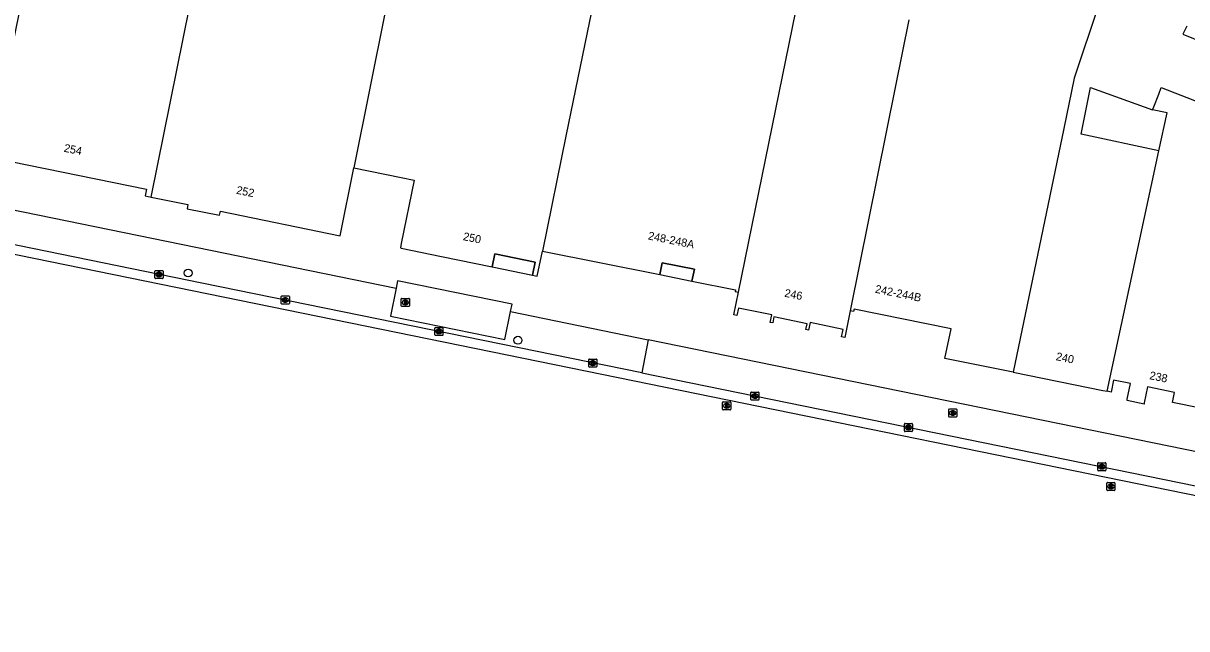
# Model space of a CAD drawing. Extents: x 158087 to 159494, y 382905 to 383981.
# Drawn here: x 158453.1 to 158597.5, y 383022.1 to 383097.3 of the extents above; entities that cross this region are included whole.
import ezdxf

# ---------------------------------------------------------------- set-up
doc = ezdxf.new("R2010")
doc.units = 0
for name, color, linetype in [('IMGEO_Boom', 7, 'Continuous'), ('IMGEO_Brandkraan', 7, 'Continuous'), ('IMGEO_Kolk', 7, 'Continuous'), ('IMGEO_Pand', 7, 'Continuous'), ('IMGEO_Pand_nummerreeks', 7, 'Continuous'), ('IMGEO_Pand_overbouw', 7, 'Continuous'), ('IMGEO_Parkeervlak_open', 7, 'Continuous'), ('IMGEO_Rijbaan_lokaal_gesloten', 7, 'Continuous'), ('IMGEO_Rioolput', 7, 'Continuous'), ('IMGEO_Voetpad_open', 7, 'Continuous')]:
    doc.layers.add(name, color=color, linetype=linetype)

msp = doc.modelspace()

# ---------------------------------------------------------------- linework, layer by layer
at = {"layer": 'IMGEO_Boom'}
for centre in [(158473.55, 383066.24), (158514.48, 383057.89)]:
    msp.add_circle(centre, 0.489, dxfattribs=at)
at = {"layer": 'IMGEO_Brandkraan'}
for p, q in [((158500, 383062.16), (158500, 383063.02)), ((158500.08, 383063.09), (158500.93, 383063.09)), ((158500.93, 383062.09), (158500.08, 383062.09)), ((158500.49, 383062.87), (158500.52, 383062.87)), ((158500.51, 383062.31), (158500.49, 383062.31)), ((158501.01, 383063.02), (158501.01, 383062.16)), ((158567.96, 383048.43), (158567.96, 383049.28)), ((158568.03, 383049.36), (158568.88, 383049.36)), ((158568.45, 383049.13), (158568.47, 383049.13)), ((158568.96, 383049.28), (158568.96, 383048.43)), ((158568.88, 383048.35), (158568.03, 383048.35)), ((158568.47, 383048.58), (158568.44, 383048.58))]:
    msp.add_line(p, q, dxfattribs=at)
for points in [[(158500, 383062.16), (158500, 383063.02)], [(158500.08, 383063.09), (158500.93, 383063.09)], [(158500.93, 383062.09), (158500.08, 383062.09)], [(158500.35, 383062.79), (158500.35, 383062.39), (158500.57, 383062.39)], [(158500.58, 383062.79), (158500.35, 383062.79)], [(158500.53, 383062.71), (158500.48, 383062.71), (158500.48, 383062.63)], [(158500.48, 383062.63), (158500.53, 383062.63)], [(158500.54, 383062.56), (158500.48, 383062.56), (158500.48, 383062.48)], [(158500.48, 383062.48), (158500.54, 383062.48)], [(158501.01, 383063.02), (158501.01, 383062.16)], [(158567.96, 383048.43), (158567.96, 383049.28)], [(158568.03, 383049.36), (158568.88, 383049.36)], [(158568.96, 383049.28), (158568.96, 383048.43)], [(158568.88, 383048.35), (158568.03, 383048.35)], [(158568.3, 383049.05), (158568.3, 383048.65), (158568.52, 383048.65)], [(158568.54, 383049.05), (158568.3, 383049.05)], [(158568.48, 383048.97), (158568.43, 383048.97), (158568.43, 383048.9)], [(158568.43, 383048.9), (158568.48, 383048.9)], [(158568.49, 383048.82), (158568.43, 383048.82), (158568.43, 383048.74)], [(158568.43, 383048.74), (158568.49, 383048.74)]]:
    msp.add_lwpolyline(points, dxfattribs=at)
for centre, radius, start, end in [((158500.08, 383063.02), 0.0765, 91.552, 178.448), ((158500.08, 383063.02), 0.0765, 91.552, 178.448), ((158500.08, 383062.17), 0.0765, 181.552, 268.448), ((158500.08, 383062.17), 0.0765, 181.552, 268.448), ((158500.53, 383062.67), 0.0379, 267.8285, 90.9355), ((158500.54, 383062.52), 0.0404, 269.8759, 90.5077), ((158500.57, 383062.64), 0.251, 268.6676, 293.5347), ((158500.59, 383062.65), 0.145, 59.4692, 91.5367), ((158500.61, 383062.69), 0.0922, 285.5137, 58.1501), ((158500.62, 383062.5), 0.105, 301.3115, 78.989), ((158500.93, 383063.02), 0.0765, 1.552, 88.448), ((158500.93, 383063.02), 0.0765, 1.552, 88.448), ((158500.93, 383062.17), 0.0765, 271.552, 358.448), ((158500.93, 383062.17), 0.0765, 271.552, 358.448), ((158568.03, 383049.28), 0.0765, 91.552, 178.448), ((158568.03, 383049.28), 0.0765, 91.552, 178.448), ((158568.88, 383049.28), 0.0765, 1.552, 88.448), ((158568.88, 383049.28), 0.0765, 1.552, 88.448), ((158568.03, 383048.43), 0.0765, 181.552, 268.448), ((158568.03, 383048.43), 0.0765, 181.552, 268.448), ((158568.48, 383048.94), 0.0379, 267.8285, 90.9355), ((158568.49, 383048.78), 0.0404, 269.8759, 90.5077), ((158568.52, 383048.91), 0.251, 268.6676, 293.5347), ((158568.54, 383048.91), 0.145, 59.4692, 91.5367), ((158568.57, 383048.96), 0.0922, 285.5137, 58.1501), ((158568.57, 383048.77), 0.105, 301.3115, 78.989), ((158568.88, 383048.43), 0.0765, 271.552, 358.448), ((158568.88, 383048.43), 0.0765, 271.552, 358.448)]:
    msp.add_arc(centre, radius, start, end, dxfattribs=at)
for centre, major_axis, ratio, start_param, end_param in [((158500.49, 383062.59), (-0.387, 0.002), 0.722429, 4.712389, 7.853982), ((158500.52, 383062.59), (-0.39, 0.002), 0.717154, 1.570796, 4.712389), ((158568.44, 383048.85), (-0.387, 0.002), 0.722429, 4.712389, 7.853982), ((158568.47, 383048.85), (-0.39, 0.002), 0.717154, 1.570796, 4.712389)]:
    msp.add_ellipse(centre, major_axis=major_axis, ratio=ratio, start_param=start_param, end_param=end_param, dxfattribs=at)
at = {"layer": 'IMGEO_Kolk'}
for p, q in [((158469.43, 383065.63), (158469.43, 383066.48)), ((158469.51, 383066.56), (158470.36, 383066.56)), ((158470.43, 383066.48), (158470.43, 383065.63)), ((158470.36, 383065.56), (158469.51, 383065.56)), ((158469.92, 383066.34), (158469.95, 383066.34)), ((158469.94, 383065.78), (158469.92, 383065.78)), ((158485.1, 383062.47), (158485.1, 383063.32)), ((158485.18, 383063.4), (158486.03, 383063.4)), ((158486.03, 383062.39), (158485.18, 383062.39)), ((158485.59, 383063.17), (158485.62, 383063.17)), ((158485.61, 383062.62), (158485.59, 383062.62)), ((158486.11, 383063.32), (158486.11, 383062.47)), ((158504.18, 383058.56), (158504.18, 383059.41)), ((158504.26, 383059.49), (158505.11, 383059.49)), ((158504.67, 383059.27), (158504.7, 383059.27)), ((158505.18, 383059.41), (158505.18, 383058.56)), ((158505.11, 383058.49), (158504.26, 383058.49)), ((158504.69, 383058.71), (158504.67, 383058.71)), ((158523.28, 383054.63), (158523.28, 383055.48)), ((158523.35, 383055.55), (158524.2, 383055.55)), ((158523.77, 383055.33), (158523.79, 383055.33)), ((158524.28, 383055.48), (158524.28, 383054.63)), ((158524.2, 383054.55), (158523.35, 383054.55)), ((158523.79, 383054.77), (158523.76, 383054.77)), ((158543.4, 383050.53), (158543.4, 383051.39)), ((158543.47, 383051.46), (158544.33, 383051.46)), ((158543.89, 383051.24), (158543.91, 383051.24)), ((158543.91, 383050.68), (158543.89, 383050.68)), ((158544.4, 383051.39), (158544.4, 383050.53)), ((158544.33, 383050.46), (158543.47, 383050.46)), ((158562.46, 383046.63), (158562.46, 383047.48)), ((158562.53, 383047.56), (158563.39, 383047.56)), ((158563.39, 383046.56), (158562.53, 383046.56)), ((158562.97, 383046.78), (158562.94, 383046.78)), ((158562.95, 383047.34), (158562.97, 383047.34)), ((158563.46, 383047.48), (158563.46, 383046.63)), ((158586.46, 383041.76), (158586.46, 383042.61)), ((158586.53, 383042.68), (158587.38, 383042.68)), ((158586.94, 383042.46), (158586.97, 383042.46)), ((158586.97, 383041.9), (158586.94, 383041.9)), ((158587.46, 383042.61), (158587.46, 383041.76)), ((158587.38, 383041.68), (158586.53, 383041.68))]:
    msp.add_line(p, q, dxfattribs=at)
for points in [[(158469.43, 383065.63), (158469.43, 383066.48)], [(158469.51, 383066.56), (158470.36, 383066.56)], [(158470.43, 383066.48), (158470.43, 383065.63)], [(158470.36, 383065.56), (158469.51, 383065.56)], [(158469.75, 383066.26), (158469.88, 383066.26), (158469.88, 383066.11), (158470.01, 383066.26), (158470.17, 383066.26), (158470.03, 383066.11), (158470.18, 383065.86), (158470.03, 383065.86), (158469.94, 383066.02), (158469.88, 383065.95), (158469.88, 383065.86), (158469.75, 383065.86), (158469.75, 383066.26)], [(158485.1, 383062.47), (158485.1, 383063.32)], [(158485.18, 383063.4), (158486.03, 383063.4)], [(158486.03, 383062.39), (158485.18, 383062.39)], [(158485.42, 383063.09), (158485.55, 383063.09), (158485.55, 383062.94), (158485.68, 383063.09), (158485.84, 383063.09), (158485.7, 383062.94), (158485.85, 383062.69), (158485.7, 383062.69), (158485.61, 383062.86), (158485.55, 383062.79), (158485.55, 383062.69), (158485.42, 383062.69), (158485.42, 383063.09)], [(158486.11, 383063.32), (158486.11, 383062.47)], [(158504.18, 383058.56), (158504.18, 383059.41)], [(158504.26, 383059.49), (158505.11, 383059.49)], [(158505.18, 383059.41), (158505.18, 383058.56)], [(158505.11, 383058.49), (158504.26, 383058.49)], [(158504.5, 383059.19), (158504.63, 383059.19), (158504.63, 383059.03), (158504.76, 383059.19), (158504.92, 383059.19), (158504.77, 383059.04), (158504.93, 383058.79), (158504.77, 383058.79), (158504.69, 383058.95), (158504.63, 383058.88), (158504.63, 383058.79), (158504.5, 383058.79), (158504.5, 383059.19)], [(158523.28, 383054.63), (158523.28, 383055.48)], [(158523.35, 383055.55), (158524.2, 383055.55)], [(158523.6, 383055.25), (158523.72, 383055.25), (158523.72, 383055.1), (158523.85, 383055.25), (158524.02, 383055.25), (158523.87, 383055.1), (158524.02, 383054.85), (158523.87, 383054.85), (158523.79, 383055.02), (158523.72, 383054.95), (158523.72, 383054.85), (158523.6, 383054.85), (158523.6, 383055.25)], [(158524.28, 383055.48), (158524.28, 383054.63)], [(158524.2, 383054.55), (158523.35, 383054.55)], [(158543.4, 383050.53), (158543.4, 383051.39)], [(158543.47, 383051.46), (158544.33, 383051.46)], [(158543.72, 383051.16), (158543.84, 383051.16), (158543.84, 383051.01), (158543.97, 383051.16), (158544.14, 383051.16), (158543.99, 383051.01), (158544.14, 383050.76), (158543.99, 383050.76), (158543.91, 383050.92), (158543.84, 383050.86), (158543.84, 383050.76), (158543.72, 383050.76), (158543.72, 383051.16)], [(158544.4, 383051.39), (158544.4, 383050.53)], [(158544.33, 383050.46), (158543.47, 383050.46)], [(158562.46, 383046.63), (158562.46, 383047.48)], [(158562.53, 383047.56), (158563.39, 383047.56)], [(158563.39, 383046.56), (158562.53, 383046.56)], [(158562.78, 383047.26), (158562.9, 383047.26), (158562.9, 383047.1), (158563.03, 383047.26), (158563.2, 383047.26), (158563.05, 383047.11), (158563.2, 383046.86), (158563.05, 383046.86), (158562.97, 383047.02), (158562.9, 383046.95), (158562.9, 383046.86), (158562.78, 383046.86), (158562.78, 383047.26)], [(158563.46, 383047.48), (158563.46, 383046.63)], [(158586.46, 383041.76), (158586.46, 383042.61)], [(158586.53, 383042.68), (158587.38, 383042.68)], [(158586.78, 383042.38), (158586.9, 383042.38), (158586.9, 383042.23), (158587.03, 383042.38), (158587.19, 383042.38), (158587.05, 383042.23), (158587.2, 383041.98), (158587.05, 383041.98), (158586.96, 383042.15), (158586.9, 383042.08), (158586.9, 383041.98), (158586.78, 383041.98), (158586.78, 383042.38)], [(158587.46, 383042.61), (158587.46, 383041.76)], [(158587.38, 383041.68), (158586.53, 383041.68)]]:
    msp.add_lwpolyline(points, dxfattribs=at)
for centre, start, end in [((158469.51, 383066.48), 91.552, 178.448), ((158469.51, 383066.48), 91.552, 178.448), ((158470.36, 383066.48), 1.552, 88.448), ((158470.36, 383066.48), 1.552, 88.448), ((158469.51, 383065.63), 181.552, 268.448), ((158469.51, 383065.63), 181.552, 268.448), ((158470.36, 383065.63), 271.552, 358.448), ((158470.36, 383065.63), 271.552, 358.448), ((158485.18, 383063.32), 91.552, 178.448), ((158485.18, 383063.32), 91.552, 178.448), ((158485.18, 383062.47), 181.552, 268.448), ((158485.18, 383062.47), 181.552, 268.448), ((158486.03, 383063.32), 1.552, 88.448), ((158486.03, 383063.32), 1.552, 88.448), ((158486.03, 383062.47), 271.552, 358.448), ((158486.03, 383062.47), 271.552, 358.448), ((158504.26, 383059.41), 91.552, 178.448), ((158504.26, 383059.41), 91.552, 178.448), ((158505.11, 383059.41), 1.552, 88.448), ((158505.11, 383059.41), 1.552, 88.448), ((158504.26, 383058.56), 181.552, 268.448), ((158504.26, 383058.56), 181.552, 268.448), ((158505.11, 383058.56), 271.552, 358.448), ((158505.11, 383058.56), 271.552, 358.448), ((158523.35, 383055.48), 91.552, 178.448), ((158523.35, 383055.48), 91.552, 178.448), ((158524.2, 383055.48), 1.552, 88.448), ((158524.2, 383055.48), 1.552, 88.448), ((158523.35, 383054.63), 181.552, 268.448), ((158523.35, 383054.63), 181.552, 268.448), ((158524.2, 383054.63), 271.552, 358.448), ((158524.2, 383054.63), 271.552, 358.448), ((158543.48, 383051.38), 91.552, 178.448), ((158543.48, 383051.38), 91.552, 178.448), ((158543.48, 383050.54), 181.552, 268.448), ((158543.48, 383050.54), 181.552, 268.448), ((158544.32, 383051.38), 1.552, 88.448), ((158544.32, 383051.38), 1.552, 88.448), ((158544.32, 383050.54), 271.552, 358.448), ((158544.32, 383050.54), 271.552, 358.448), ((158562.53, 383047.48), 91.552, 178.448), ((158562.53, 383047.48), 91.552, 178.448), ((158562.53, 383046.63), 181.552, 268.448), ((158562.53, 383046.63), 181.552, 268.448), ((158563.38, 383047.48), 1.552, 88.448), ((158563.38, 383047.48), 1.552, 88.448), ((158563.38, 383046.63), 271.552, 358.448), ((158563.38, 383046.63), 271.552, 358.448), ((158586.53, 383042.61), 91.552, 178.448), ((158586.53, 383042.61), 91.552, 178.448), ((158587.38, 383042.61), 1.552, 88.448), ((158587.38, 383042.61), 1.552, 88.448), ((158586.53, 383041.76), 181.552, 268.448), ((158586.53, 383041.76), 181.552, 268.448), ((158587.38, 383041.76), 271.552, 358.448), ((158587.38, 383041.76), 271.552, 358.448)]:
    msp.add_arc(centre, 0.0765, start, end, dxfattribs=at)
for centre, major_axis, ratio, start_param, end_param in [((158469.92, 383066.06), (-0.387, 0.002), 0.722429, 4.712389, 7.853982), ((158469.94, 383066.06), (-0.39, 0.002), 0.717154, 1.570796, 4.712389), ((158485.59, 383062.89), (-0.387, 0.002), 0.722429, 4.712389, 7.853982), ((158485.62, 383062.89), (-0.39, 0.002), 0.717154, 1.570796, 4.712389), ((158504.67, 383058.99), (-0.387, 0.002), 0.722429, 4.712389, 7.853982), ((158504.69, 383058.99), (-0.39, 0.002), 0.717154, 1.570796, 4.712389), ((158523.76, 383055.05), (-0.387, 0.002), 0.722429, 4.712389, 7.853982), ((158523.79, 383055.05), (-0.39, 0.002), 0.717154, 1.570796, 4.712389), ((158543.89, 383050.96), (-0.387, 0.002), 0.722429, 4.712389, 7.853982), ((158543.91, 383050.96), (-0.39, 0.002), 0.717154, 1.570796, 4.712389), ((158562.95, 383047.06), (-0.387, 0.002), 0.722429, 4.712389, 7.853982), ((158562.97, 383047.06), (-0.39, 0.002), 0.717154, 1.570796, 4.712389), ((158586.94, 383042.18), (-0.387, 0.002), 0.722429, 4.712389, 7.853982), ((158586.97, 383042.18), (-0.39, 0.002), 0.717154, 1.570796, 4.712389)]:
    msp.add_ellipse(centre, major_axis=major_axis, ratio=ratio, start_param=start_param, end_param=end_param, dxfattribs=at)
at = {"layer": 'IMGEO_Pand'}
for points in [[(158479.18, 383126.28), (158479.24, 383126.6), (158458.57, 383128.06), (158455.24, 383111.69), (158450.36, 383087.66), (158450.14, 383087.71), (158449.59, 383085.07), (158448.56, 383080.17), (158448.4, 383080.21), (158448.31, 383079.79), (158448.73, 383079.7), (158448.75, 383079.8), (158449.3, 383079.69), (158449.46, 383080.49), (158468.37, 383076.65), (158468.21, 383075.82), (158468.97, 383075.66)], [(158468.97, 383075.66), (158478.57, 383123.25), (158478.97, 383125.22), (158479.18, 383126.28)], [(158503.18, 383124.09), (158502.39, 383120.51), (158500, 383108.63), (158494.11, 383079.31)], [(158527.76, 383119.04), (158526.18, 383111.25), (158520.49, 383083.45), (158517.52, 383068.95)], [(158541.86, 383063.86), (158550.27, 383105.1)], [(158586.57, 383099.61), (158583.53, 383090.45), (158582.26, 383084.19), (158575.96, 383053.92)], [(158563.01, 383097.7), (158561.35, 383089.48), (158555.74, 383061.55)], [(158597.51, 383096.89), (158597, 383095.92), (158599.66, 383094.83), (158609.63, 383090.77), (158607.15, 383084.29), (158601.64, 383086.43)], [(158594.04, 383081.42), (158584.4, 383083.5), (158585.57, 383089.28), (158593.24, 383086.51)], [(158593.24, 383086.51), (158593.4, 383086.9), (158594.02, 383088.44), (158594.34, 383089.27), (158601.64, 383086.43)], [(158594.04, 383081.42), (158595.06, 383086.12), (158593.24, 383086.51)], [(158587.61, 383051.55), (158594.04, 383081.42)], [(158468.97, 383075.66), (158473.51, 383074.74), (158473.41, 383074.23), (158477.44, 383073.41), (158477.55, 383073.92), (158492.42, 383070.88), (158494.11, 383079.31)], [(158494.11, 383079.31), (158500, 383078.12), (158501.61, 383077.79), (158500, 383069.89), (158499.89, 383069.35), (158500, 383069.33), (158505.01, 383068.3), (158511.29, 383067), (158511.63, 383068.63), (158516.64, 383067.6), (158516.31, 383065.99), (158516.68, 383065.91), (158516.89, 383065.87), (158517.52, 383068.95)], [(158517.52, 383068.95), (158532.1, 383066.04), (158532.39, 383067.49), (158536.38, 383066.7), (158536.08, 383065.25), (158541.5, 383064.16), (158541.45, 383063.94), (158541.86, 383063.86)], [(158555.74, 383061.55), (158555.06, 383058.23), (158554.66, 383058.31), (158554.85, 383059.24), (158550.74, 383060.08), (158550.55, 383059.15), (158550.23, 383059.21), (158550.38, 383059.95), (158546.26, 383060.79), (158546.11, 383060.05), (158545.8, 383060.11), (158545.99, 383061.05), (158541.85, 383061.89), (158541.66, 383060.96), (158541.29, 383061.03), (158541.86, 383063.86)], [(158575.96, 383053.92), (158567.49, 383055.64), (158568.24, 383059.32), (158556.2, 383061.77), (158556.13, 383061.47), (158555.74, 383061.55)], [(158575.96, 383053.92), (158587.09, 383051.66), (158587.61, 383051.55)], [(158599.7, 383049.09), (158599.14, 383049.21), (158599.19, 383049.44), (158595.72, 383050.15), (158595.98, 383051.41), (158592.63, 383052.09), (158592.23, 383050.13), (158592.2, 383049.96), (158590.09, 383050.39), (158590.12, 383050.56), (158590.52, 383052.52), (158588.42, 383052.95), (158588.12, 383051.45), (158587.61, 383051.55)]]:
    msp.add_lwpolyline(points, dxfattribs=at)
at = {"layer": 'IMGEO_Pand_overbouw'}
for points in [[(158511.29, 383067), (158516.31, 383065.99), (158516.64, 383067.6), (158511.63, 383068.63)], [(158536.08, 383065.25), (158536.38, 383066.7), (158532.39, 383067.49), (158532.1, 383066.04)]]:
    msp.add_lwpolyline(points, close=True, dxfattribs=at)
at = {"layer": 'IMGEO_Parkeervlak_open'}
msp.add_lwpolyline([(158513.57, 383061.45), (158513.76, 383062.38), (158499.55, 383065.28), (158499.36, 383064.35)], dxfattribs=at)
at = {"layer": 'IMGEO_Rijbaan_lokaal_gesloten'}
for points in [[(158529.87, 383053.84), (158475.26, 383065), (158450.8, 383070), (158430.76, 383074.2), (158409.76, 383078.87), (158398.8, 383081.36), (158378.84, 383086.04), (158349.97, 383093.09), (158331.07, 383097.86), (158314.15, 383102.24), (158309.73, 383103.47), (158294.41, 383107.71)], [(158679.45, 383022.06), (158450.55, 383068.82), (158430.51, 383073.03), (158409.5, 383077.7), (158387.58, 383082.73), (158368.61, 383087.26), (158349.68, 383091.93), (158330.77, 383096.7), (158313.84, 383101.08), (158294.05, 383106.59)], [(158529.87, 383053.84), (158679.69, 383023.23)]]:
    msp.add_lwpolyline(points, dxfattribs=at)
at = {"layer": 'IMGEO_Rioolput'}
for p, q in [((158539.89, 383049.32), (158539.89, 383050.17)), ((158539.97, 383050.25), (158540.82, 383050.25)), ((158540.82, 383049.25), (158539.97, 383049.25)), ((158540.38, 383050.03), (158540.41, 383050.03)), ((158540.4, 383049.47), (158540.38, 383049.47)), ((158540.9, 383050.17), (158540.9, 383049.32)), ((158587.59, 383039.3), (158587.59, 383040.15)), ((158587.66, 383040.23), (158588.52, 383040.23)), ((158588.52, 383039.23), (158587.66, 383039.23)), ((158588.1, 383039.45), (158588.07, 383039.45)), ((158588.08, 383040.01), (158588.1, 383040.01)), ((158588.59, 383040.15), (158588.59, 383039.3))]:
    msp.add_line(p, q, dxfattribs=at)
for points in [[(158539.89, 383049.32), (158539.89, 383050.17)], [(158539.97, 383050.25), (158540.82, 383050.25)], [(158540.82, 383049.25), (158539.97, 383049.25)], [(158540.48, 383049.95), (158540.23, 383049.95), (158540.23, 383049.55)], [(158540.23, 383049.55), (158540.36, 383049.55), (158540.36, 383049.71), (158540.37, 383049.71)], [(158540.41, 383049.87), (158540.36, 383049.87), (158540.36, 383049.79)], [(158540.36, 383049.79), (158540.41, 383049.79)], [(158540.41, 383049.68), (158540.48, 383049.55), (158540.62, 383049.55), (158540.56, 383049.67)], [(158540.9, 383050.17), (158540.9, 383049.32)], [(158587.59, 383039.3), (158587.59, 383040.15)], [(158587.66, 383040.23), (158588.52, 383040.23)], [(158588.52, 383039.23), (158587.66, 383039.23)], [(158588.18, 383039.92), (158587.92, 383039.93), (158587.92, 383039.53)], [(158587.92, 383039.53), (158588.05, 383039.53), (158588.05, 383039.69), (158588.06, 383039.69)], [(158588.1, 383039.85), (158588.05, 383039.85), (158588.05, 383039.76)], [(158588.05, 383039.76), (158588.1, 383039.76)], [(158588.11, 383039.66), (158588.18, 383039.53), (158588.32, 383039.53), (158588.25, 383039.65)], [(158588.59, 383040.15), (158588.59, 383039.3)]]:
    msp.add_lwpolyline(points, dxfattribs=at)
for centre, radius, start, end in [((158539.97, 383050.17), 0.0765, 91.552, 178.448), ((158539.97, 383050.17), 0.0765, 91.552, 178.448), ((158539.97, 383049.32), 0.0765, 181.552, 268.448), ((158539.97, 383049.32), 0.0765, 181.552, 268.448), ((158540.36, 383049.66), 0.0533, 26.0293, 88.6989), ((158540.41, 383049.77), 0.0964, 77.0061, 93.1865), ((158540.39, 383049.98), 0.19, 274.7715, 282.9687), ((158540.43, 383049.83), 0.0378, 276.6634, 79.6772), ((158540.48, 383049.84), 0.109, 350.3612, 89.416), ((158540.48, 383049.84), 0.112, 277.5842, 350.9817), ((158540.46, 383049.62), 0.108, 29.5134, 73.7905), ((158540.82, 383050.17), 0.0765, 1.552, 88.448), ((158540.82, 383050.17), 0.0765, 1.552, 88.448), ((158540.82, 383049.32), 0.0765, 271.552, 358.448), ((158540.82, 383049.32), 0.0765, 271.552, 358.448), ((158587.66, 383040.15), 0.0765, 91.552, 178.448), ((158587.66, 383040.15), 0.0765, 91.552, 178.448), ((158587.66, 383039.3), 0.0765, 181.552, 268.448), ((158587.66, 383039.3), 0.0765, 181.552, 268.448), ((158588.06, 383039.64), 0.0533, 26.0293, 88.6989), ((158588.11, 383039.75), 0.0964, 77.0061, 93.1865), ((158588.09, 383039.95), 0.19, 274.7715, 282.9687), ((158588.12, 383039.81), 0.0378, 276.6634, 79.6772), ((158588.18, 383039.82), 0.109, 350.3612, 89.416), ((158588.17, 383039.81), 0.112, 277.5842, 350.9817), ((158588.16, 383039.6), 0.108, 29.5134, 73.7905), ((158588.51, 383040.15), 0.0765, 1.552, 88.448), ((158588.51, 383040.15), 0.0765, 1.552, 88.448), ((158588.51, 383039.3), 0.0765, 271.552, 358.448), ((158588.51, 383039.3), 0.0765, 271.552, 358.448)]:
    msp.add_arc(centre, radius, start, end, dxfattribs=at)
for centre, major_axis, ratio, start_param, end_param in [((158540.38, 383049.75), (-0.387, 0.002), 0.722429, 4.712389, 7.853982), ((158540.41, 383049.75), (-0.39, 0.002), 0.717154, 1.570796, 4.712389), ((158588.08, 383039.73), (-0.387, 0.002), 0.722429, 4.712389, 7.853982), ((158588.1, 383039.73), (-0.39, 0.002), 0.717154, 1.570796, 4.712389)]:
    msp.add_ellipse(centre, major_axis=major_axis, ratio=ratio, start_param=start_param, end_param=end_param, dxfattribs=at)
at = {"layer": 'IMGEO_Voetpad_open'}
for points in [[(158275.71, 383117.34), (158282.35, 383115.44), (158303.64, 383109.43), (158319.19, 383105.27), (158367.17, 383093.16), (158387.94, 383088.19), (158416.66, 383081.61), (158447.77, 383074.9), (158499.36, 383064.35)], [(158499.36, 383064.35), (158498.66, 383060.88), (158512.86, 383057.98), (158513.57, 383061.45)], [(158513.57, 383061.45), (158530.65, 383057.96)], [(158530.65, 383057.96), (158529.87, 383053.84)], [(158636.41, 383036.34), (158530.65, 383057.96)]]:
    msp.add_lwpolyline(points, dxfattribs=at)

# ---------------------------------------------------------------- texts
at = {"layer": 'IMGEO_Pand_nummerreeks'}
for s, rotation, p in [('254', 348.5179, (158458.07, 383081.32)), ('252', 348.4721, (158479.46, 383076.1)), ('250', 348.4205, (158507.61, 383070.34)), ('248-248A', 348.707, (158530.58, 383070.42)), ('246', 348.5028, (158547.5, 383063.31)), ('242-244B', 348.5948, (158558.75, 383063.81)), ('240', 348.5122, (158581.2, 383055.43)), ('238', 348.5065, (158592.81, 383053.07))]:
    msp.add_text(s, height=1, rotation=rotation, dxfattribs=at).set_placement(p)

doc.saveas('drawing.dxf')
